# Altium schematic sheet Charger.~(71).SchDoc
size A3; SheetNumber: 2; SheetTotal: 2
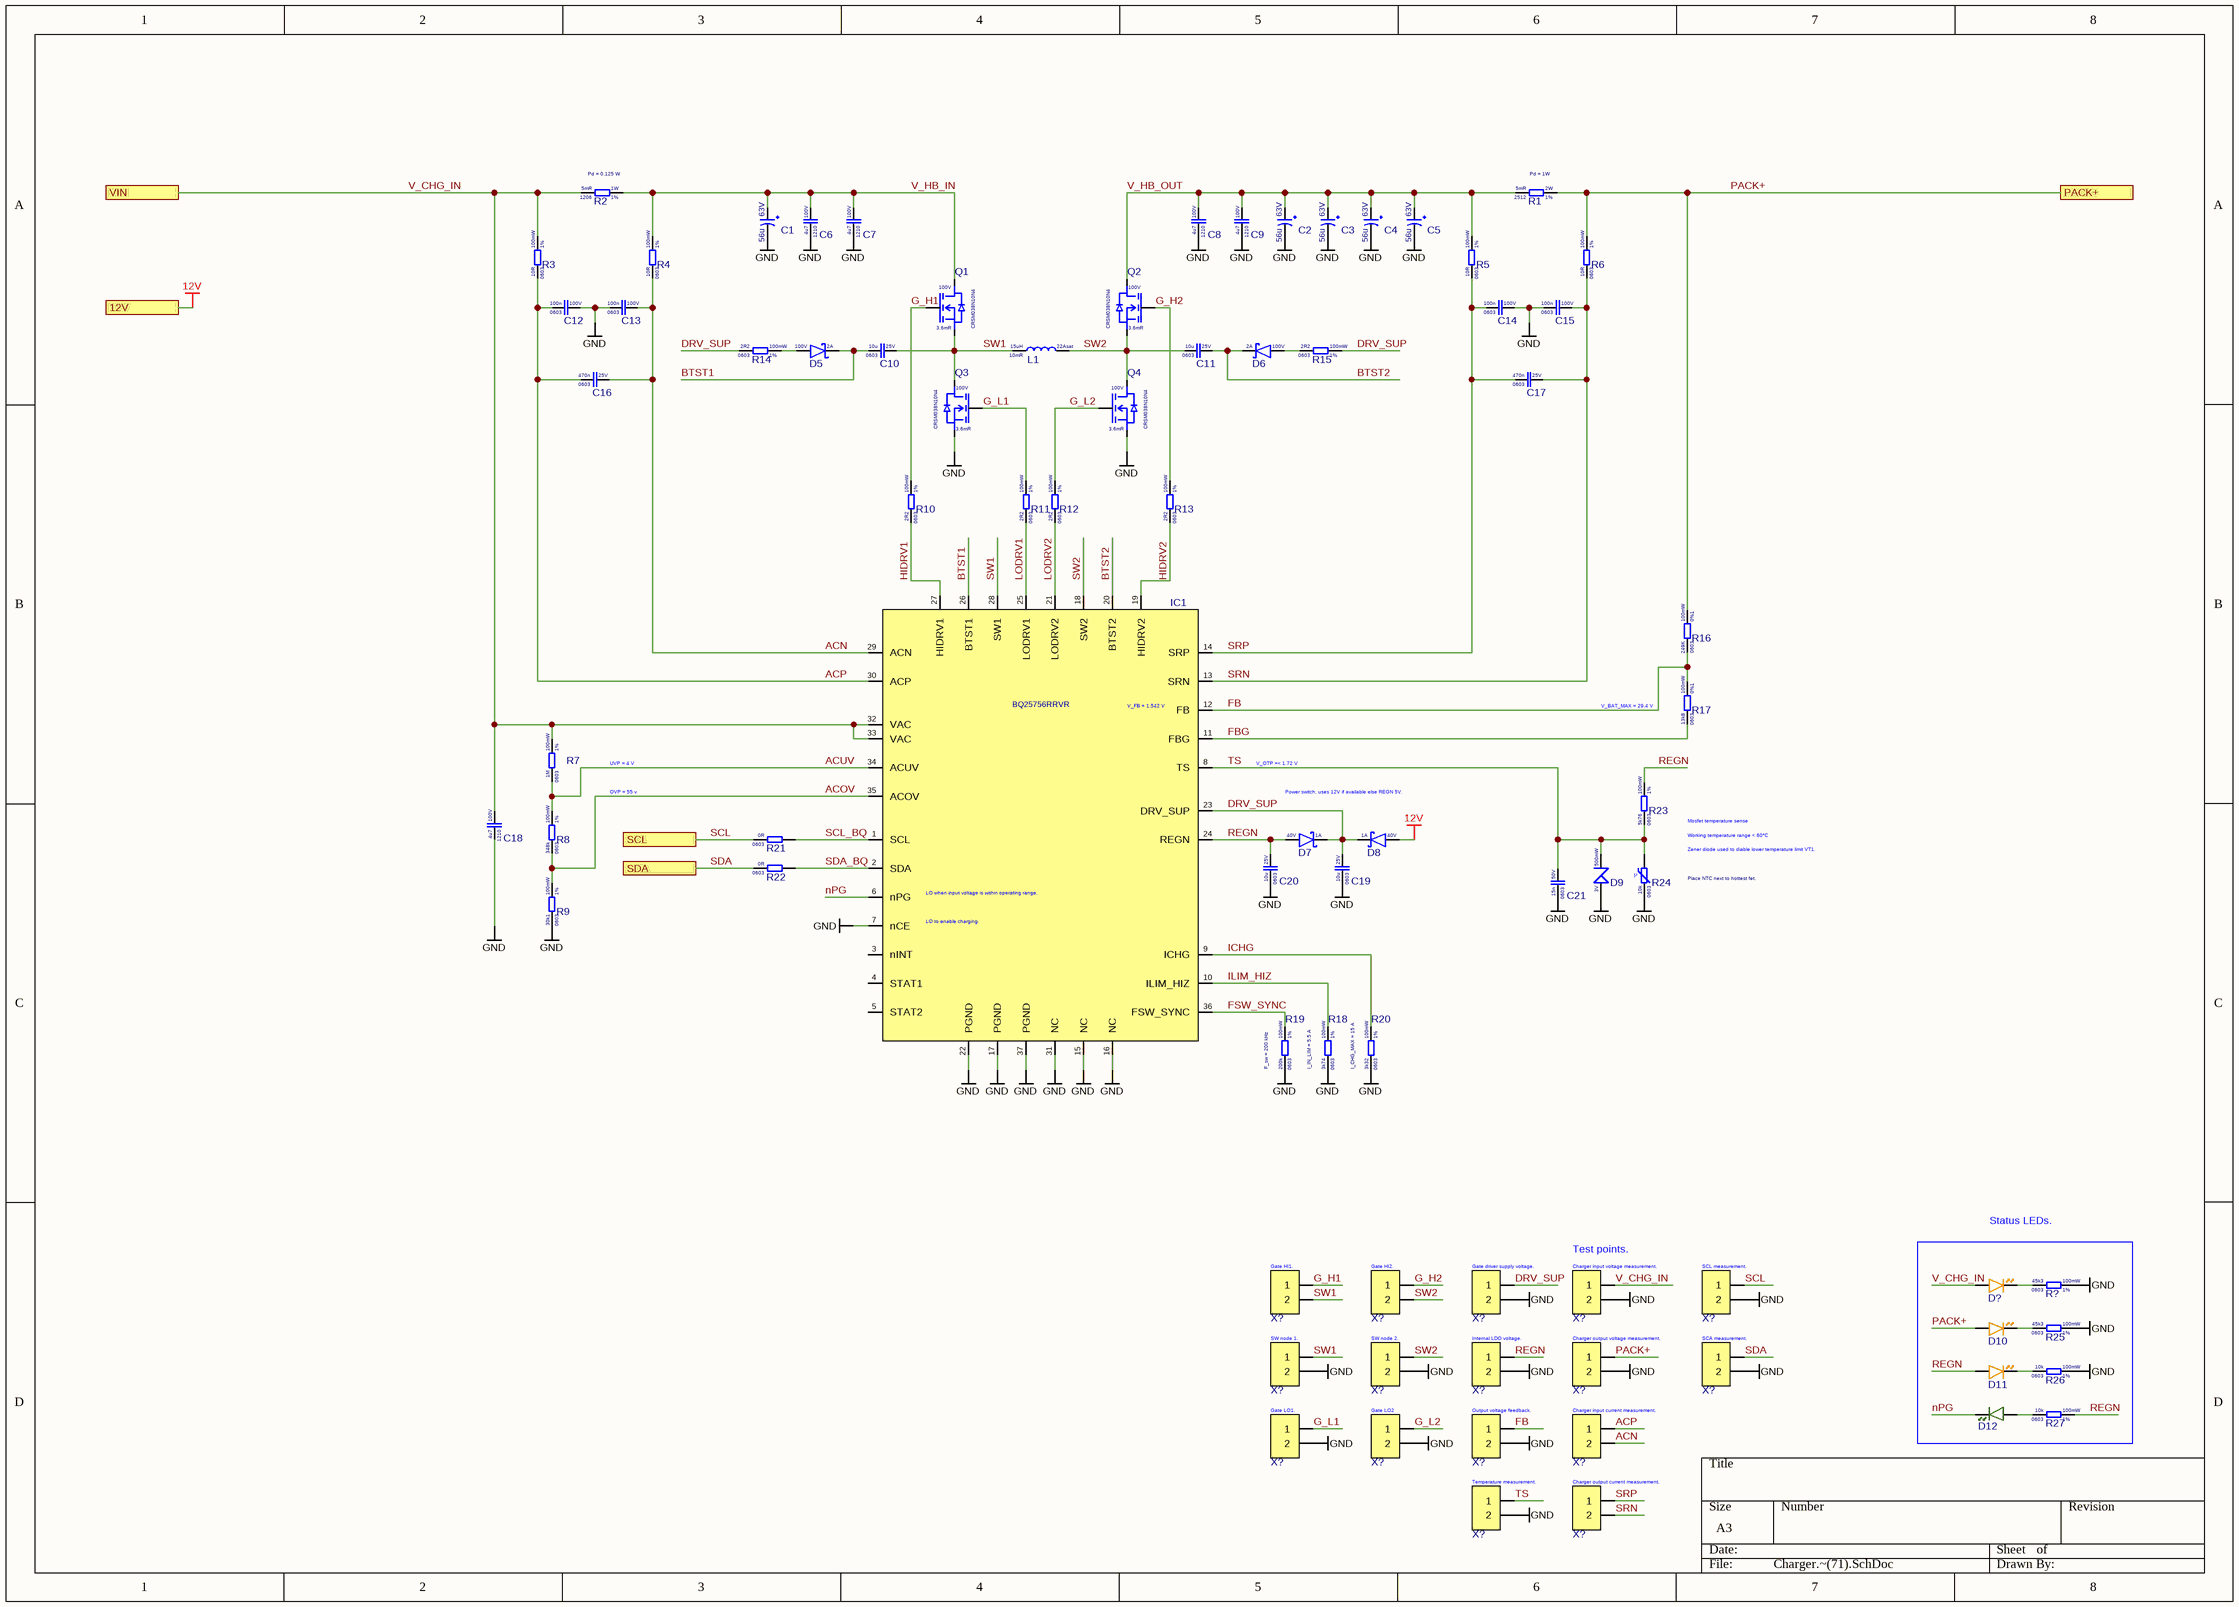
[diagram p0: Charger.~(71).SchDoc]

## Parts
(Parts that share a designator on the sheet are numbered #1, #2 ... from top to bottom, then left to right.)
C1  Voltage Rating: 63V  Capacitance: 56u  [CAP_SMD_10X10.2]  (hidden comment: EEHZA1J560P)
C2  Voltage Rating: 63V  Capacitance: 56u  [CAP_SMD_10X10.2]  (hidden comment: EEHZA1J560P)
C3  Voltage Rating: 63V  Capacitance: 56u  [CAP_SMD_10X10.2]  (hidden comment: EEHZA1J560P)
C4  Voltage Rating: 63V  Capacitance: 56u  [CAP_SMD_10X10.2]  (hidden comment: EEHZA1J560P)
C5  Voltage Rating: 63V  Capacitance: 56u  [CAP_SMD_10X10.2]  (hidden comment: EEHZA1J560P)
C6  Voltage Rating: 100V  Case Code (Imperial): 1210  Capacitance: 4u7  [CAP_1210]  (hidden comment: HMK325C7475KN-TE)
C7  Voltage Rating: 100V  Case Code (Imperial): 1210  Capacitance: 4u7  [CAP_1210]  (hidden comment: HMK325C7475KN-TE)
C8  Voltage Rating: 100V  Case Code (Imperial): 1210  Capacitance: 4u7  [CAP_1210]  (hidden comment: HMK325C7475KN-TE)
C9  Voltage Rating: 100V  Case Code (Imperial): 1210  Capacitance: 4u7  [CAP_1210]  (hidden comment: HMK325C7475KN-TE)
C10  Voltage Rating: 25V  Case Code (Imperial): 0603  Capacitance: 10u  [CAP 0603]  (hidden comment: CL10A106MA8NRNC)
C11  Voltage Rating: 25V  Case Code (Imperial): 0603  Capacitance: 10u  [CAP 0603]  (hidden comment: CL10A106MA8NRNC)
C12  Voltage Rating: 100V  Case Code (Imperial): 0603  Capacitance: 100n  [CAP 0603]  (hidden comment: CC0603KRX7R0BB104)
C13  Voltage Rating: 100V  Case Code (Imperial): 0603  Capacitance: 100n  [CAP 0603]  (hidden comment: CC0603KRX7R0BB104)
C14  Voltage Rating: 100V  Case Code (Imperial): 0603  Capacitance: 100n  [CAP 0603]  (hidden comment: CC0603KRX7R0BB104)
C15  Voltage Rating: 100V  Case Code (Imperial): 0603  Capacitance: 100n  [CAP 0603]  (hidden comment: CC0603KRX7R0BB104)
C16  Voltage Rating: 25V  Case Code (Imperial): 0603  Capacitance: 470n  [CAP 0603]  (hidden comment: CL10B474KA8NNNC)
C17  Voltage Rating: 25V  Case Code (Imperial): 0603  Capacitance: 470n  [CAP 0603]  (hidden comment: CL10B474KA8NNNC)
C18  Voltage Rating: 100V  Case Code (Imperial): 1210  Capacitance: 4u7  [CAP_1210]  (hidden comment: HMK325C7475KN-TE)
C19  Voltage Rating: 25V  Case Code (Imperial): 0603  Capacitance: 10u  [CAP 0603]  (hidden comment: CL10A106MA8NRNC)
C20  Voltage Rating: 25V  Case Code (Imperial): 0603  Capacitance: 10u  [CAP 0603]  (hidden comment: CL10A106MA8NRNC)
C21  Voltage Rating: 50V  Case Code (Imperial): 0603  Capacitance: 15n  [CAP 0603]  (hidden comment: CC0603KRX7R9BB153)
D5  Forward Current: 2A  Reverse Voltage: 100V  [SMAF]  (hidden comment: SS210F)
D6  Forward Current: 2A  Reverse Voltage: 100V  [SMAF]  (hidden comment: SS210F)
D7  Forward Current: 1A  Reverse Voltage: 40V  [SOD-323]  (hidden comment: 1N5819WS)
D8  Forward Current: 1A  Reverse Voltage: 40V  [SOD-323]  (hidden comment: 1N5819WS)
D9  Power Rating: 500mW  Reverse Voltage: 3V  [SOD-123]  (hidden comment: BZT52C3V0)
D10  XL-1608UOC-06  [DIODE_0603]  (value not drawn)
D11  XL-1608UOC-06  [DIODE_0603]  (value not drawn)
D12  PSC-1608U52GC-G4  [DIODE_0603]  (value not drawn)
D?  XL-1608UOC-06  [DIODE_0603]  (value not drawn)
IC1  BQ25756RRVR  [VQFN-36(5x6)]
L1  Resistance: 10mR  Saturation current: 22Asat  Inductance: 15uH  [MTF1810-150M]  (hidden comment: MTF1810-150M)
Q1  Rds: 3.6mR  Voltage: 100V  [DFN-8 (5x6)]  (hidden comment: CRSM038N10N4)
Q2  Rds: 3.6mR  Voltage: 100V  [DFN-8 (5x6)]  (hidden comment: CRSM038N10N4)
Q3  Rds: 3.6mR  Voltage: 100V  [DFN-8 (5x6)]  (hidden comment: CRSM038N10N4)
Q4  Rds: 3.6mR  Voltage: 100V  [DFN-8 (5x6)]  (hidden comment: CRSM038N10N4)
R1  Pd = 1W  Resistance Tolerance: 1%  Resistance: 5mR  Power Rating: 2W  Case Code (Imperial): 2512  [RES_2512]
R2  Pd = 0.125 W  Resistance Tolerance: 1%  Resistance: 5mR  Power Rating: 1W  Case Code (Imperial): 1206  [RES_1206]
R3  Resistance Tolerance: 1%  Resistance: 10R  Power Rating: 100mW  Case Code (Imperial): 0603  [RES_0603]  (hidden comment: 0603WAF100JT5E)
R4  Resistance Tolerance: 1%  Resistance: 10R  Power Rating: 100mW  Case Code (Imperial): 0603  [RES_0603]  (hidden comment: 0603WAF100JT5E)
R5  Resistance Tolerance: 1%  Resistance: 10R  Power Rating: 100mW  Case Code (Imperial): 0603  [RES_0603]  (hidden comment: 0603WAF100JT5E)
R6  Resistance Tolerance: 1%  Resistance: 10R  Power Rating: 100mW  Case Code (Imperial): 0603  [RES_0603]  (hidden comment: 0603WAF100JT5E)
R7  Resistance Tolerance: 1%  Resistance: 1M  Power Rating: 100mW  Case Code (Imperial): 0603  [RES_0603]  (hidden comment: 0603WAF1004T5E)
R8  Resistance Tolerance: 1%  Resistance: 348k  Power Rating: 100mW  Case Code (Imperial): 0603  [RES_0603]  (hidden comment: 0603WAF3483T5E)
R9  Resistance Tolerance: 1%  Resistance: 30k1  Power Rating: 100mW  Case Code (Imperial): 0603  [RES_0603]  (hidden comment: 0603WAF3012T5E)
R10  Resistance Tolerance: 1%  Resistance: 2R2  Power Rating: 100mW  Case Code (Imperial): 0603  [RES_0603]  (hidden comment: 0603WAF220KT5E)
R11  Resistance Tolerance: 1%  Resistance: 2R2  Power Rating: 100mW  Case Code (Imperial): 0603  [RES_0603]  (hidden comment: 0603WAF220KT5E)
R12  Resistance Tolerance: 1%  Resistance: 2R2  Power Rating: 100mW  Case Code (Imperial): 0603  [RES_0603]  (hidden comment: 0603WAF220KT5E)
R13  Resistance Tolerance: 1%  Resistance: 2R2  Power Rating: 100mW  Case Code (Imperial): 0603  [RES_0603]  (hidden comment: 0603WAF220KT5E)
R14  Resistance Tolerance: 1%  Resistance: 2R2  Power Rating: 100mW  Case Code (Imperial): 0603  [RES_0603]  (hidden comment: 0603WAF220KT5E)
R15  Resistance Tolerance: 1%  Resistance: 2R2  Power Rating: 100mW  Case Code (Imperial): 0603  [RES_0603]  (hidden comment: 0603WAF220KT5E)
R16  Resistance Tolerance: 0%1  Resistance: 249K  Power Rating: 100mW  Case Code (Imperial): 0603  [RES_0603]  (hidden comment: RT0603BRD07249KL)
R17  Resistance Tolerance: 0%1  Resistance: 13k8  Power Rating: 100mW  Case Code (Imperial): 0603  [RES_0603]  (hidden comment: RT0603BRD0713K8L)
R18  I_IN_LIM = 5.5 A  Resistance Tolerance: 1%  Resistance: 3k74  Power Rating: 100mW  Case Code (Imperial): 0603  [RES_0603]
R19  F_sw = 200 kHz  Resistance Tolerance: 1%  Resistance: 200k  Power Rating: 100mW  Case Code (Imperial): 0603  [RES_0603]
R20  I_CHG_MAX = 15 A  Resistance Tolerance: 1%  Resistance: 3k32  Power Rating: 100mW  Case Code (Imperial): 0603  [RES_0603]
R21  Resistance: 0R  Case Code (Imperial): 0603  [RES_0603]  (hidden comment: 0603WAF0000T5E)
R22  Resistance: 0R  Case Code (Imperial): 0603  [RES_0603]  (hidden comment: 0603WAF0000T5E)
R23  Resistance Tolerance: 1%  Resistance: 5k76  Power Rating: 100mW  Case Code (Imperial): 0603  [RES_0603]  (hidden comment: 0603WAF5761T5E)
R24  Place NTC next to hottest fet.  Resistance: 10k  Case Code (Imperial): 0603  [RES_0603]
R25  Resistance Tolerance: 1%  Resistance: 45k3  Power Rating: 100mW  Case Code (Imperial): 0603  [RES_0603]  (hidden comment: 0603WAF4532T5E)
R26  Resistance Tolerance: 1%  Resistance: 10k  Power Rating: 100mW  Case Code (Imperial): 0603  [RES_0603]  (hidden comment: 0603WAF1002T5E)
R27  Resistance Tolerance: 1%  Resistance: 10k  Power Rating: 100mW  Case Code (Imperial): 0603  [RES_0603]  (hidden comment: 0603WAF1002T5E)
R?  Resistance Tolerance: 1%  Resistance: 45k3  Power Rating: 100mW  Case Code (Imperial): 0603  [RES_0603]  (hidden comment: 0603WAF4532T5E)
X?#1  ZX-PZ1.27-1-2PZZ  [Pin header 1x2 1.27mmP THT Vertical]  (value not drawn)
X?#2  ZX-PZ1.27-1-2PZZ  [Pin header 1x2 1.27mmP THT Vertical]  (value not drawn)
X?#3  ZX-PZ1.27-1-2PZZ  [Pin header 1x2 1.27mmP THT Vertical]  (value not drawn)
X?#4  ZX-PZ1.27-1-2PZZ  [Pin header 1x2 1.27mmP THT Vertical]  (value not drawn)
X?#5  ZX-PZ1.27-1-2PZZ  [Pin header 1x2 1.27mmP THT Vertical]  (value not drawn)
X?#6  ZX-PZ1.27-1-2PZZ  [Pin header 1x2 1.27mmP THT Vertical]  (value not drawn)
X?#7  ZX-PZ1.27-1-2PZZ  [Pin header 1x2 1.27mmP THT Vertical]  (value not drawn)
X?#8  ZX-PZ1.27-1-2PZZ  [Pin header 1x2 1.27mmP THT Vertical]  (value not drawn)
X?#9  ZX-PZ1.27-1-2PZZ  [Pin header 1x2 1.27mmP THT Vertical]  (value not drawn)
X?#10  ZX-PZ1.27-1-2PZZ  [Pin header 1x2 1.27mmP THT Vertical]  (value not drawn)
X?#11  ZX-PZ1.27-1-2PZZ  [Pin header 1x2 1.27mmP THT Vertical]  (value not drawn)
X?#12  ZX-PZ1.27-1-2PZZ  [Pin header 1x2 1.27mmP THT Vertical]  (value not drawn)
X?#13  ZX-PZ1.27-1-2PZZ  [Pin header 1x2 1.27mmP THT Vertical]  (value not drawn)
X?#14  ZX-PZ1.27-1-2PZZ  [Pin header 1x2 1.27mmP THT Vertical]  (value not drawn)
X?#15  ZX-PZ1.27-1-2PZZ  [Pin header 1x2 1.27mmP THT Vertical]  (value not drawn)
X?#16  ZX-PZ1.27-1-2PZZ  [Pin header 1x2 1.27mmP THT Vertical]  (value not drawn)

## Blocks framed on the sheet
Status LEDs.: D10-D12 D? R25-R27 R?

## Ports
12V (see Arhitecture[5B]), PACK+ (see Arhitecture[6B]), SCL (see Arhitecture[5B]), SDA (see Arhitecture[5B]), VIN (see Arhitecture[5B])

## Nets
12V: D8.A ; port 12V
GND: C1.- C2.- C3.- C4.- C5.- C6.1 C7.1 C8.1 C9.1 C12.2 C13.1 C14.2 C15.1 C18.1 C19.1 C20.1 C21.1 D9.A IC1.7(nCE) IC1.15(NC) IC1.16(NC) IC1.17(PGND) IC1.22(PGND) IC1.31(NC) IC1.37(PGND) Q3.S Q4.S R9.1 R18.1 R19.1 R20.1 R24.1 R25.2 R26.2 R?.2 X?#3.2 X?#4.2 X?#5.2 X?#6.2 X?#7.2 X?#8.2 X?#9.2 X?#10.2 X?#11.2 X?#12.2 X?#13.2 X?#15.2
ACN: C13.2 C16.2 IC1.29(ACN) R4.1 X?#14.2
ACOV: IC1.35(ACOV) R8.1 R9.2
ACP: C12.1 C16.1 IC1.30(ACP) R3.1 X?#14.1
ACUV: IC1.34(ACUV) R7.1 R8.2
BTST1: C10.1 D5.K IC1.26(BTST1)
BTST2: C11.2 D6.K IC1.20(BTST2)
DRV_SUP: C19.2 D7.K D8.K IC1.23(DRV_SUP) R14.1 R15.2 X?#3.1
FB: IC1.12(FB) R16.1 R17.2 X?#13.1
FBG: IC1.11(FBG) R17.1
FSW_SYNC: IC1.36(FSW_SYNC) R19.2
G_H1: Q1.G R10.2 X?#1.1
G_H2: Q2.G R13.2 X?#2.1
G_L1: Q3.G R11.2 X?#11.1
G_L2: Q4.G R12.2 X?#12.1
HIDRV1: IC1.27(HIDRV1) R10.1
HIDRV2: IC1.19(HIDRV2) R13.1
ICHG: IC1.9(ICHG) R20.2
ILIM_HIZ: IC1.10(ILIM_HIZ) R18.2
LODRV1: IC1.25(LODRV1) R11.1
LODRV2: IC1.21(LODRV2) R12.1
nPG: D12.K IC1.6(nPG)
PACK+: D10.A R1.2 R6.2 R16.2 X?#9.1 ; port PACK+
REGN: C20.2 D7.A D11.A IC1.24(REGN) R23.2 R27.2 X?#8.1
SCL: R21.1 X?#5.1 ; port SCL
SCL_BQ: IC1.1(SCL) R21.2
SDA: R22.1 X?#10.1 ; port SDA
SDA_BQ: IC1.2(SDA) R22.2
SRN: C15.2 C17.2 IC1.13(SRN) R6.1 X?#16.2
SRP: C14.1 C17.1 IC1.14(SRP) R5.1 X?#16.1
SW1: C10.2 IC1.28(SW1) L1.1 Q1.S Q3.D X?#1.2 X?#6.1
SW2: C11.1 IC1.18(SW2) L1.2 Q2.S Q4.D X?#2.2 X?#7.1
TS: C21.2 D9.K IC1.8(TS) R23.1 R24.2 X?#15.1
V_CHG_IN: C18.2 D?.A IC1.32(VAC) IC1.33(VAC) R2.1 R3.2 R7.2 X?#4.1 ; port VIN
V_HB_IN: C1.+ C6.2 C7.2 Q1.D R2.2 R4.2
V_HB_OUT: C2.+ C3.+ C4.+ C5.+ C8.2 C9.2 Q2.D R1.1 R5.2
NetD5_A: D5.A R14.2
NetD6_A: D6.A R15.1
NetD10_K: D10.K R25.1
NetD11_K: D11.K R26.1
NetD12_A: D12.A R27.1
NetD?_K: D?.K R?.1

Not connected (* = marked no-connect by the designer): IC1 3(nINT) 4(STAT1) 5(STAT2)

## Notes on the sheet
- UVP = 4 V
- (near IC1) V_FB = 1.542 V
- V_OTP =< 1.72 V
- (near R17) V_BAT_MAX = 29.4 V
- OVP = 55 v
- Power switch, uses 12V if available else REGN 5V.
- Mosfet temperature sense
- Working temperature range < 60°C
- (near IC1) LO when input voltage is within operating range.
- Zener diode used to diable lower temperature limit VT1.
- (near IC1) LO to enable charging.
- (near X?#1) Gate HI1.
- (near X?#2) Gate HI2.
- (near X?#3) Gate driver supply voltage.
- (near X?#4) Test points.
- (near X?#4) Charger input voltage measurement.
- (near X?#5) SCL measurement.
- (near X?#6) SW node 1.
- (near X?#7) SW node 2.
- (near X?#8) Internal LDO voltage.
- (near X?#9) Charger output voltage measurement.
- (near X?#10) SCA measurement.
- (near X?#11) Gate LO1.
- (near X?#12) Gate LO2
- (near X?#13) Output voltage feedback.
- (near X?#14) Charger input current measurement.
- (near X?#15) Temperature measurement.
- (near X?#16) Charger output current measurement.

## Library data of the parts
C1-C5 = EEHZA1J560P: Cap AL-EL 56uF 63V 30mR 1.8Ar SMD 10x10.2mm; Manufacturer: Panasonic
C6-C9 C18 = HMK325C7475KN-TE: Cap 4.7uF 100V 1210 X7R; Manufacturer: Taiyo Yuden
C10 C11 C19 C20 = CL10A106MA8NRNC: Cap 10uF 25V 0603 X5R; Manufacturer: Samsung
C12-C15 = CC0603KRX7R0BB104: Cap 100nF 100V 0603 X7R; Manufacturer: YAGEO
C16 C17 = CL10B474KA8NNNC: Cap 470nF 25V 0603 X7R; Manufacturer: Samsung
C21 = CC0603KRX7R9BB153: Cap 15nF 50V 0603 X7R; Manufacturer: Yageo; Manufacturer Part Number: CC0603KRX7R9BB104
D5 D6 = SS210F: Schottky 100V 2A 850mVf SMAF; Manufacturer: GOODWORK
D7 D8 = 1N5819WS: Schottky 40V 1A 600mVf SOD-323; Manufacturer: Guangdong Hottech
D9 = BZT52C3V0: Zener 3.0V 500mW SOD-123; Manufacturer: Shandong Jingdao Microelectronics
D10 D11 D? = XL-1608UOC-06: LED Orange 0603 20mA; Manufacturer: XINGLIGHT
D12 = PSC-1608U52GC-G4: LED Green 0603 20mA; Manufacturer: HONGLITRONIC
IC1 = BQ25756RRVR: Charger IC; Manufacturer: Texas Instruments
L1 = MTF1810-150M: Inductor 15uH 22Asat 10mR SMD 18x18x9 mm; Manufacturer: COILMX
Q1-Q4 = CRSM038N10N4: Nmos 100V 100A 3.6mR DFN-8(5x6); Manufacturer: CRMICRO
R1 = RLM25FEER005: Res 5mR 2512 1% 2W; Manufacturer: TA-I Tech
R2 = FRM121WFR005TM: Res 5mR 1206 1% 1W; Manufacturer: FOJAN
R3-R6 = 0603WAF100JT5E: Res 10R 0603 1% 100mW 75V; Manufacturer: Uni-Royal
R7 = 0603WAF1004T5E: Res 1M 0603 1% 100mW 75V; Manufacturer: Uni-Royal
R8 = 0603WAF3483T5E: Res 348k 0603 1% 100mW 75V; Manufacturer: Uni-Royal
R9 = 0603WAF3012T5E: Res 30k1 0603 1% 100mW 75V; Manufacturer: Uni-Royal
R10-R15 = 0603WAF220KT5E: Res 2R2 0603 1% 100mW 75V; Manufacturer: Uni-Royal
R16 = RT0603BRD07249KL: Res 249K 0603 0.1% 100mW 75V; Manufacturer: YAGEO
R17 = RT0603BRD0713K8L: Res 13.8k 0603 0.1% 100mW 75V; Manufacturer: YAGEO
R18 = FRC0603F3741TS: Res 3K74 0603 1% 100mW 75V; Manufacturer: FOJAN
R19 = 0603WAF2003T5E: Res 200K 0603 1% 100mW 75V; Manufacturer: UNI-ROYAL
R20 = 0603WAF3321T5E: Res 3k32 0603 1% 100mW 75V; Manufacturer: UNI-ROYAL
R21 R22 = 0603WAF0000T5E: Res 0R 0603 1% 100mW 75V; Manufacturer: UNI-ROYAL
R23 = 0603WAF5761T5E: Res 5k76 0603 1% 100mW 75V; Manufacturer: Uni-Royal
R24 = NCP18XH103F03RB: NTC 10k 0603 1% 3455K; Manufacturer: Murata
R25 R? = 0603WAF4532T5E: Res 45k3 0603 1% 100mW 75V; Manufacturer: Uni-Royal
R26 R27 = 0603WAF1002T5E: Res 10k 0603 1% 100mW 75V; Manufacturer: Uni-Royal
X?#1-X?#16 = ZX-PZ1.27-1-2PZZ: Pin header 1x2 1.27mmP THT Vertical; Manufacturer: Megastar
